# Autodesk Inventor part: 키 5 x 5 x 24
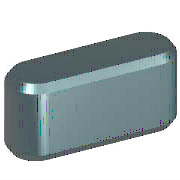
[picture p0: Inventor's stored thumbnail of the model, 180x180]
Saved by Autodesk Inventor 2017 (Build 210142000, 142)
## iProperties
IsCustomPart: 1
Created: 2012-02
Part Number: 키 5 x 5 x 24
Material: 강철, 연강
Description: 키 및 해당 키홈
Document SubType Name: Modeling
Standard: KS B 1311
Designer: mduedu
Standards Organization: KS
Language: ko-KR
Size Designation: 5 x 5 x 18
Categories: <MemberInstance><Categories><Category DisplayName="샤프트 부품" InternalName="7f7aeb1f-a693-4053-b835-cee3144e0d98" Mnemonic="SHFT"><Category DisplayName="키" Interna
Density: 7.86 g/cm^3
Appearance: 금색
Mass: 4.43866 g
Surface Area: 4.72224 cm^2
Volume: 0.564716 cm^3
Author: mduedu
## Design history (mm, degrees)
workplane "Work Plane1"
workplane "Work Plane2"
sketch "스케치1"
  geometry: L1 (2.5, 2.5)-(21.5, 2.5); L2 (21.5, -2.5)-(2.5, -2.5); L3 (0, 8.9)-(0, -4.4) reference; L4 (-3.6, 0)-(21.6, 0) reference; L5 (24, 0)-(24, 7); A1 r 2.5 centre (2.5, 0) between (2.5, 2.5) and (2.5, -2.5); A2 r 2.5 centre (21.5, 0) between (21.5, -2.5) and (21.5, 2.5)
  constraints: 6 end point, 5 point on circle, 4 tangent, 3 point on line, 2 centre point, 1 horizontal, 1 parallel, 1 perpendicular
  dimensions: "d0" = 2.5 radius of A1 (= 0.5 x PB); "d13" = 2.5 radius of A2 (= 0.5 x PB); "d14" = 24 distance between parallel lines of L5 L3 (= NLG)
extrude "본체1" new body sketch "스케치1" taper "d3" = 0 deg; stored distance "d4" = 10
workplane "Work Plane3"
body "Solid1"
chamfer "모따기1" distance "d8" = 0.4 (= PHH); stored, may be unused: second distance "d9" = 0.4 (= PHH), angle "d15" = 45 deg
other parameters: "d1" = -3 (= -PNT), "d2" = 2 (= PH - PNT), "NLG" = 24 [user parameter; used in 3 equation terms], "PB" = 5 [user parameter; used in 2 equation terms], "PNT" = 3 [user parameter; used in 2 equation terms], "PH" = 5 [user parameter; used in 1 equation term], "PHH" = 0.4 [user parameter; used in 2 equation terms], "d10" = 0, "d16" = 0, "d17" = 0, "d18" = 0, "WDMIN" = 12 [user parameter], "PLB2" = 24 (= NLG) [user parameter], "WDMAX" = 17 [user parameter], "PLB1" = 24 (= NLG) [user parameter], "RR" = 0.16 [user parameter], "PUEB" = 2.3 [user parameter]
